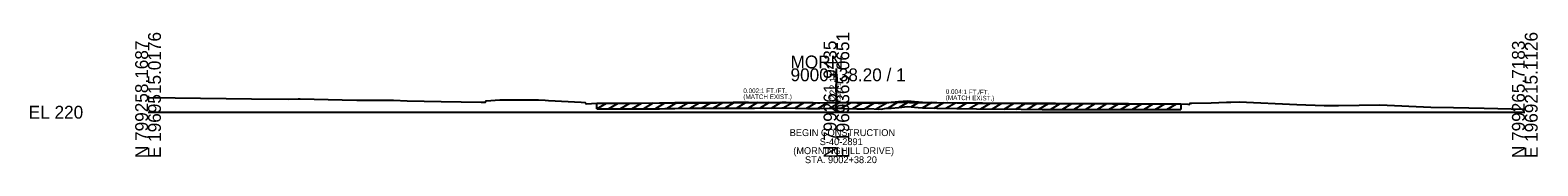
# Model space of a CAD drawing. Extents: x -26 to 2313, y -1511 to 5559.
# Drawn here: x -25.7 to 302.8, y -1511.1 to -1482.7 of the extents above; entities that cross this region are included whole.
import ezdxf

# ---------------------------------------------------------------- set-up
doc = ezdxf.new("R2010")
doc.units = 0
for name, color, linetype in [('Default', 7, 'Continuous'), ('RD_XS_ExGround', 7, 'Continuous'), ('RD_XS_ExPaveRet', 7, 'Continuous'), ('RD_XS_Misc_Line', 7, 'Continuous'), ('RD_XS_Pave', 7, 'Continuous'), ('RD_XS_TieSlope', 7, 'Continuous'), ('RD_XS_TX_Elev_EX', 7, 'Continuous'), ('RD_XS_TX_Elev_PR', 7, 'Continuous'), ('RD_XS_TX_Notes', 7, 'Continuous'), ('RD_XS_TX_Slope', 7, 'Continuous')]:
    doc.layers.add(name, color=color, linetype=linetype)

msp = doc.modelspace()

# ---------------------------------------------------------------- linework, layer by layer
at = {"layer": 'Default'}
for p, q in [((150, -1500), (150, -1490.45)), ((0, -1500), (150, -1500)), ((150, -1500), (300, -1500))]:
    msp.add_line(p, q, dxfattribs=at)
at = {"layer": 'RD_XS_ExGround'}
msp.add_lwpolyline([(0, -1496.82), (5.9, -1496.87), (22.56, -1497.07), (30.65, -1497.14), (32.69, -1497.1), (33.14, -1497.11), (42.29, -1497.29), (45.48, -1497.36), (53.48, -1497.4), (56.44, -1497.53), (63.9, -1497.69), (72.57, -1497.81), (73.55, -1497.8), (73.65, -1497.5), (76.68, -1497.33), (82.54, -1497.3), (85.09, -1497.32), (86.51, -1497.38), (87.24, -1497.41), (94.37, -1497.81), (95.25, -1497.86), (95.43, -1498.16), (97.8, -1498), (99.27, -1498.01), (100.68, -1498.02), (101.95, -1498.02), (106.82, -1498), (111.45, -1497.98), (112.58, -1497.95), (114.75, -1497.91), (118.37, -1497.85), (119.12, -1497.85), (121.24, -1497.85), (127.47, -1497.84), (130.81, -1497.84), (132.12, -1497.85), (138.13, -1497.81), (139.06, -1497.82), (141.17, -1497.88), (143.69, -1497.91), (144.94, -1497.91), (145.88, -1497.92), (146.36, -1497.93), (149.24, -1497.9), (150, -1497.89), (150.99, -1497.88), (151.62, -1497.91), (154.41, -1497.99), (156.08, -1497.98), (157.27, -1497.96), (159.08, -1498.06), (159.39, -1498.03), (159.72, -1498.06), (160.84, -1497.88), (161.45, -1497.85), (161.94, -1497.84), (163.59, -1497.69), (165.47, -1497.51), (167.8, -1497.73), (168.72, -1497.81), (171.9, -1497.85), (180.52, -1498), (190.27, -1498.09), (194.86, -1498.13), (199.18, -1498.13), (199.7, -1498.13), (202.27, -1498.13), (206.7, -1498.13), (210.19, -1498.14), (210.94, -1498.14), (213.36, -1498.14), (214.23, -1498.14), (215.89, -1498.15), (217.65, -1498.15), (218.69, -1498.15), (220.93, -1498.15), (221.4, -1498.16), (223.79, -1498.15), (225.05, -1498.15), (226.6, -1498.27), (226.95, -1498.29), (227.09, -1498.04), (227.44, -1498.04), (231.68, -1497.97), (234.97, -1497.82), (235.92, -1497.8), (237.79, -1497.77), (250.35, -1498.3), (256.31, -1498.54), (259.39, -1498.5), (268.43, -1498.37), (279.54, -1498.89), (284.47, -1498.97), (291.15, -1499.1), (300, -1499.3)], dxfattribs=at)
at = {"layer": 'RD_XS_ExPaveRet'}
for p, q in [((97.8, -1499.25), (97.8, -1498)), ((97.8, -1499.25), (99.27, -1499.26)), ((99.27, -1499.26), (100.68, -1499.27)), ((100.68, -1499.27), (101.95, -1499.27)), ((101.95, -1499.27), (106.82, -1499.25)), ((106.82, -1499.25), (111.45, -1499.23)), ((111.45, -1499.23), (112.58, -1499.2)), ((112.58, -1499.2), (114.75, -1499.16)), ((114.75, -1499.16), (118.37, -1499.1)), ((118.37, -1499.1), (119.12, -1499.1)), ((119.12, -1499.1), (121.24, -1499.1)), ((121.24, -1499.1), (127.47, -1499.09)), ((127.47, -1499.09), (130.81, -1499.09)), ((130.81, -1499.09), (132.12, -1499.1)), ((132.12, -1499.1), (138.13, -1499.06)), ((138.13, -1499.06), (139.06, -1499.07)), ((139.06, -1499.07), (141.17, -1499.13)), ((141.17, -1499.13), (143.69, -1499.16)), ((143.69, -1499.16), (144.94, -1499.16)), ((144.94, -1499.16), (145.88, -1499.17)), ((145.88, -1499.17), (146.36, -1499.18)), ((146.36, -1499.18), (149.24, -1499.15)), ((149.24, -1499.15), (150, -1499.14)), ((150, -1499.14), (150.99, -1499.13)), ((150.99, -1499.13), (151.62, -1499.16)), ((151.62, -1499.16), (154.41, -1499.24)), ((154.41, -1499.24), (156.08, -1499.23)), ((156.08, -1499.23), (157.27, -1499.21)), ((157.27, -1499.21), (159.08, -1499.31)), ((159.08, -1499.31), (159.39, -1499.28)), ((159.39, -1499.28), (159.72, -1499.31)), ((159.72, -1499.31), (160.84, -1499.13)), ((160.84, -1499.13), (161.45, -1499.1)), ((161.45, -1499.1), (161.94, -1499.09)), ((161.94, -1499.09), (163.59, -1498.94)), ((163.59, -1498.94), (165.47, -1498.76)), ((165.47, -1498.76), (167.8, -1498.98)), ((167.8, -1498.98), (168.72, -1499.06)), ((168.72, -1499.06), (171.9, -1499.1)), ((171.9, -1499.1), (180.52, -1499.25)), ((180.52, -1499.25), (190.27, -1499.34)), ((190.27, -1499.34), (194.86, -1499.38)), ((194.86, -1499.38), (199.18, -1499.38)), ((199.18, -1499.38), (199.7, -1499.38)), ((199.7, -1499.38), (202.27, -1499.38)), ((202.27, -1499.38), (206.7, -1499.38)), ((206.7, -1499.38), (210.19, -1499.39)), ((210.19, -1499.39), (210.94, -1499.39)), ((210.94, -1499.39), (213.36, -1499.39)), ((213.36, -1499.39), (214.23, -1499.39)), ((214.23, -1499.39), (215.89, -1499.4)), ((215.89, -1499.4), (217.65, -1499.4)), ((217.65, -1499.4), (218.69, -1499.4)), ((218.69, -1499.4), (220.93, -1499.4)), ((220.93, -1499.4), (221.4, -1499.41)), ((221.4, -1499.41), (223.79, -1499.4)), ((223.79, -1499.4), (225.05, -1499.4)), ((225.05, -1498.15), (225.05, -1499.4))]:
    msp.add_line(p, q, dxfattribs=at)
at = {"layer": 'RD_XS_Misc_Line'}
for p, q in [((97.8, -1499.25), (99.89, -1498.01)), ((100.34, -1499.27), (102.44, -1498.02)), ((102.87, -1499.27), (105, -1498.01)), ((105.41, -1499.26), (107.54, -1498)), ((107.94, -1499.24), (110.08, -1497.98)), ((110.48, -1499.23), (112.64, -1497.95)), ((113.01, -1499.2), (115.2, -1497.9)), ((115.55, -1499.15), (117.73, -1497.86)), ((118.08, -1499.1), (120.2, -1497.85)), ((120.62, -1499.1), (122.73, -1497.85)), ((123.15, -1499.1), (125.27, -1497.85)), ((125.69, -1499.1), (127.8, -1497.84)), ((128.22, -1499.09), (130.34, -1497.84)), ((130.76, -1499.09), (132.88, -1497.84)), ((133.29, -1499.09), (135.42, -1497.83)), ((135.83, -1499.08), (137.96, -1497.82)), ((138.36, -1499.07), (140.4, -1497.86)), ((140.9, -1499.12), (142.96, -1497.91)), ((143.43, -1499.16), (145.54, -1497.92)), ((145.97, -1499.17), (148.1, -1497.91)), ((148.5, -1499.15), (150.65, -1497.88)), ((151.04, -1499.13), (153.04, -1497.95)), ((153.57, -1499.22), (155.66, -1497.98)), ((156.11, -1499.23), (158.16, -1498.01)), ((158.64, -1499.29), (161.04, -1497.87)), ((161.18, -1499.11), (163.58, -1497.69)), ((163.71, -1498.93), (166.02, -1497.57)), ((166.25, -1498.84), (168.07, -1497.76)), ((168.78, -1499.07), (170.85, -1497.84)), ((171.32, -1499.1), (173.38, -1497.88)), ((173.85, -1499.14), (175.91, -1497.92)), ((176.39, -1499.18), (178.44, -1497.96)), ((178.92, -1499.22), (180.98, -1498)), ((181.46, -1499.26), (183.54, -1498.03)), ((183.99, -1499.28), (186.07, -1498.05)), ((186.53, -1499.3), (188.61, -1498.07)), ((189.06, -1499.33), (191.14, -1498.1)), ((191.6, -1499.35), (193.68, -1498.12)), ((194.13, -1499.37), (196.23, -1498.13)), ((196.67, -1499.38), (198.78, -1498.13)), ((199.2, -1499.38), (201.32, -1498.13)), ((201.74, -1499.38), (203.85, -1498.13)), ((204.27, -1499.38), (206.38, -1498.13)), ((206.81, -1499.38), (208.91, -1498.13)), ((209.34, -1499.38), (211.45, -1498.14)), ((211.88, -1499.39), (213.98, -1498.14)), ((214.41, -1499.4), (216.52, -1498.15)), ((216.95, -1499.4), (219.05, -1498.15)), ((219.48, -1499.4), (221.59, -1498.16)), ((222.02, -1499.41), (224.13, -1498.15))]:
    msp.add_line(p, q, dxfattribs=at)
at = {"layer": 'RD_XS_Pave'}
for p in [(97.8, -1498), (213.67, -1498.14)]:
    msp.add_line(p, (150, -1497.89), dxfattribs=at)
at = {"layer": 'RD_XS_TieSlope'}
msp.add_line((235.59, -1497.83), (235.66, -1497.81), dxfattribs=at)

# ---------------------------------------------------------------- texts
at = {"layer": 'Default'}
for s, p in [('N 799258.1687', (0, -1510)), ('E 1969515.0176', (2.8, -1510)), ('N 799261.9435', (150, -1510)), ('E 1969365.0651', (152.8, -1510)), ('N 799265.7183', (300, -1510)), ('E 1969215.1126', (302.8, -1510))]:
    msp.add_text(s, height=2.8, rotation=90, dxfattribs=at).set_placement(p)
for s, p in [('MORN', (140, -1490.45)), ('9000+38.20 / 1', (140, -1493.25)), ('EL 220', (-26, -1501.4))]:
    msp.add_text(s, height=2.8, dxfattribs=at).set_placement(p)
at = {"layer": 'RD_XS_TX_Elev_EX'}
msp.add_text('222.11', height=1, rotation=90, dxfattribs=at).set_placement((151.01, -1497.89))
at = {"layer": 'RD_XS_TX_Elev_PR'}
msp.add_text(' 222.11', height=1.5, rotation=90, dxfattribs=at).set_placement((150, -1497.89))
at = {"layer": 'RD_XS_TX_Notes'}
for s, p in [('BEGIN CONSTRUCTION', (139.82, -1505.2)), ('(MORNINGHILL DRIVE)', (140.59, -1509.13)), ('S-40-2891', (146.36, -1507.17)), ('STA. 9002+38.20', (143.15, -1511.1))]:
    msp.add_text(s, height=1.5, dxfattribs=at).set_placement(p)
at = {"layer": 'RD_XS_TX_Slope'}
for s, rotation, p in [('0.002:1 FT./FT.', 360, (129.71, -1495.82)), ('(MATCH EXIST.)', 360, (129.71, -1497.13)), ('0.004:1 FT./FT.', 359.1819, (173.82, -1496)), ('(MATCH EXIST.)', 359.1819, (173.81, -1497.31))]:
    msp.add_text(s, height=1, rotation=rotation, dxfattribs=at).set_placement(p)

doc.saveas('drawing.dxf')
